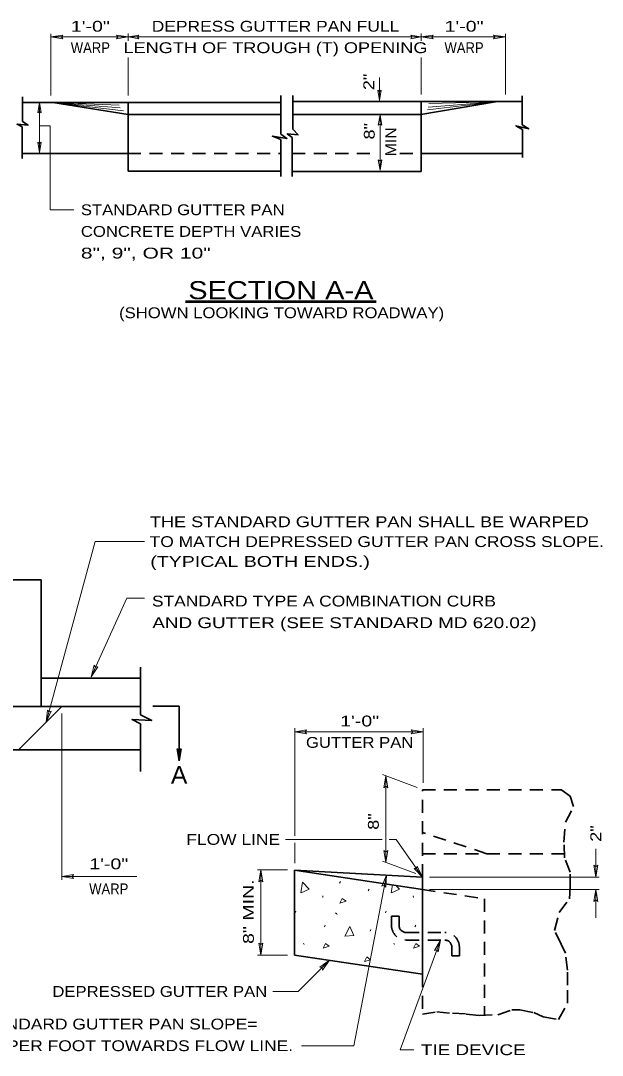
# Model space of a CAD drawing. Extents: x 16.6 to 31.7, y 5.4 to 26.
# Drawn here: x 24.24 to 31.09, y 13.23 to 25.41 of the extents above; entities that cross this region are included whole.
import ezdxf
from ezdxf.enums import TextEntityAlignment as Align

# ---------------------------------------------------------------- set-up
doc = ezdxf.new("R2010")
doc.units = 0
doc.header["$LTSCALE"] = 0.051
doc.linetypes.add('MEDIUM_DASHED', pattern=[4.5, 3, -1.5])
for name, color, linetype, lineweight in [('1', 7, 'Continuous', 35), ('10', 7, 'Continuous', 13), ('12', 7, 'Continuous', 53), ('13', 7, 'Continuous', 53), ('6', 7, 'Continuous', 13)]:
    doc.layers.add(name, color=color, linetype=linetype, lineweight=lineweight)

msp = doc.modelspace()

# ---------------------------------------------------------------- linework, layer by layer
at = {"layer": '1'}
for p, q in [((24.26392, 24.22625), (24.26392, 24.51833)), ((27.30342, 24.07883), (27.30342, 24.53325)), ((27.44408, 24.13575), (27.44408, 24.53325)), ((30.14442, 24.18958), (30.14442, 24.53058)), ((24.26875, 24.45258), (27.29925, 24.45258)), ((25.509, 24.30858), (24.62108, 24.45167)), ((25.51, 23.64292), (25.51, 24.44658)), ((27.44858, 24.46108), (30.14583, 24.46108)), ((28.95183, 24.31083), (29.82983, 24.45925)), ((28.95633, 23.63992), (28.95633, 24.46108)), ((25.509, 24.30858), (27.29758, 24.30858)), ((27.44217, 24.31083), (28.95183, 24.31083)), ((24.26208, 23.79), (24.26208, 24.16542)), ((30.14808, 23.80342), (30.14808, 24.133)), ((27.30567, 23.57792), (27.30567, 24.0135)), ((27.4395, 23.57792), (27.4395, 24.03975)), ((24.25933, 23.852), (25.5065, 23.852)), ((28.95933, 23.852), (30.1435, 23.852)), ((25.51, 23.64292), (27.30467, 23.64292)), ((27.43967, 23.63992), (28.95633, 23.63992)), ((24.48625, 18.82992), (19.43833, 18.82992)), ((24.48625, 17.33783), (24.48625, 18.82992)), ((25.65375, 17.24208), (25.65375, 17.80275)), ((25.65375, 17.67183), (24.48625, 17.67183)), ((17.99208, 17.33783), (25.65375, 17.33783)), ((24.22067, 16.8315), (24.727, 17.33783)), ((25.65333, 16.57325), (25.65333, 17.13392)), ((25.65333, 16.82675), (17.98792, 16.82675)), ((27.46475, 14.41217), (27.46475, 15.41217)), ((28.9705, 15.32908), (27.46475, 15.41217)), ((27.46475, 15.41217), (28.97017, 15.18408)), ((28.97017, 14.18642), (28.97017, 15.32908)), ((28.97017, 14.18642), (27.46475, 14.41217))]:
    msp.add_line(p, q, dxfattribs=at)
at = {"layer": '1', "linetype": 'MEDIUM_DASHED'}
for p, q in [((25.5065, 23.852), (27.30567, 23.852)), ((27.4395, 23.852), (28.42958, 23.852)), ((28.70233, 23.852), (28.95633, 23.852)), ((28.97017, 16.35567), (30.61067, 16.35567)), ((28.97017, 15.32908), (28.97017, 16.35567)), ((29.72633, 15.60483), (28.97017, 15.85692)), ((28.97017, 15.60483), (30.64092, 15.60483)), ((28.97017, 15.18392), (29.7005, 15.07333)), ((29.7005, 15.07333), (29.7005, 13.69533)), ((28.60692, 14.76075), (28.60692, 14.87092)), ((28.60692, 14.87092), (28.69567, 14.87092)), ((28.69567, 14.76075), (28.69567, 14.87092)), ((28.779, 14.67742), (29.23542, 14.67742)), ((28.779, 14.58867), (29.23242, 14.58867)), ((29.31575, 14.50533), (29.31575, 14.40183)), ((29.4045, 14.50533), (29.4045, 14.40183)), ((29.31575, 14.40183), (29.4045, 14.40183)), ((28.97017, 14.18642), (28.97017, 13.71692))]:
    msp.add_line(p, q, dxfattribs=at)
at = {"layer": '1'}
for points in [[(27.4395, 24.03975), (27.38025, 24.08283), (27.507, 24.06875), (27.44408, 24.13575)], [(27.30567, 24.0135), (27.20583, 24.05292), (27.37533, 24.028), (27.30342, 24.07883)]]:
    msp.add_lwpolyline(points, dxfattribs=at)
at = {"layer": '1', "linetype": 'MEDIUM_DASHED'}
msp.add_lwpolyline([(28.97017, 13.71692), (29.13767, 13.74208), (29.32375, 13.72592), (29.48567, 13.71783), (29.63942, 13.70167), (29.858, 13.70983), (30.01992, 13.76617), (30.117, 13.76617), (30.27892, 13.73392), (30.39217, 13.68558), (30.57025, 13.65333), (30.67542, 13.84683), (30.67542, 14.05658), (30.67542, 14.23392), (30.65117, 14.43558), (30.60267, 14.54033), (30.52167, 14.70158), (30.57825, 14.91133), (30.69975, 15.07258), (30.70775, 15.20967), (30.70775, 15.38708), (30.643, 15.55642), (30.635, 15.74183), (30.65117, 15.97567), (30.74825, 16.16117), (30.70775, 16.28217), (30.61067, 16.35467)], dxfattribs=at)
for centre, radius, start, end in [((28.779, 14.76075), 0.17208, 180, 270), ((28.779, 14.76075), 0.08333, 180, 270), ((29.23242, 14.50533), 0.17211, 0, 90), ((29.23242, 14.50533), 0.08333, 0, 90)]:
    msp.add_arc(centre, radius, start, end, dxfattribs=at)
at = {"layer": '10'}
for p, q in [((24.60033, 24.535), (24.60033, 25.25742)), ((24.74033, 25.2455), (24.60033, 25.22217)), ((25.51, 25.22217), (24.60033, 25.22217)), ((24.74033, 25.19883), (24.60033, 25.22217)), ((24.74033, 25.2455), (24.72283, 25.22217)), ((24.74033, 25.19883), (24.72283, 25.22217)), ((25.37, 25.2455), (25.51, 25.22217)), ((25.37, 25.2455), (25.3875, 25.22217)), ((25.37, 25.19883), (25.51, 25.22217)), ((25.37, 25.19883), (25.3875, 25.22217)), ((25.51, 25.17658), (25.51, 25.26333)), ((25.63358, 25.24217), (25.51358, 25.22217)), ((25.51358, 25.22217), (28.95175, 25.22217)), ((25.63358, 25.20217), (25.51358, 25.22217)), ((25.63358, 25.24217), (25.61858, 25.22217)), ((25.63358, 25.20217), (25.61858, 25.22217)), ((28.83175, 25.24217), (28.95175, 25.22217)), ((28.83175, 25.24217), (28.84675, 25.22217)), ((28.83175, 25.20217), (28.95175, 25.22217)), ((28.83175, 25.20217), (28.84675, 25.22217)), ((28.95633, 25.17658), (28.95633, 25.26333)), ((29.09633, 25.2455), (28.95633, 25.22217)), ((28.95633, 25.22217), (29.94533, 25.22217)), ((29.09633, 25.19883), (28.95633, 25.22217)), ((29.09633, 25.2455), (29.07883, 25.22217)), ((29.09633, 25.19883), (29.07883, 25.22217)), ((29.80533, 25.2455), (29.94533, 25.22217)), ((29.80533, 25.2455), (29.82283, 25.22217)), ((29.80533, 25.19883), (29.94533, 25.22217)), ((29.80533, 25.19883), (29.82283, 25.22217)), ((29.94533, 24.54442), (29.94533, 25.25742)), ((25.51, 24.535), (25.51, 24.97967)), ((28.95633, 24.54442), (28.95633, 24.97967)), ((28.46508, 24.476), (28.46508, 24.74675)), ((28.44508, 24.596), (28.46508, 24.476)), ((28.44508, 24.596), (28.46508, 24.581)), ((28.48508, 24.596), (28.46508, 24.476)), ((28.48508, 24.596), (28.46508, 24.581)), ((24.44442, 24.331), (24.46442, 24.451)), ((24.46442, 23.86208), (24.46442, 24.451)), ((24.48442, 24.331), (24.46442, 24.451)), ((24.44442, 24.331), (24.46442, 24.346)), ((24.48442, 24.331), (24.46442, 24.346)), ((28.45125, 24.18242), (28.47125, 24.30242)), ((28.47125, 23.65458), (28.47125, 24.30242)), ((28.49125, 24.18242), (28.47125, 24.30242)), ((28.45125, 24.18242), (28.47125, 24.19742)), ((28.49125, 24.18242), (28.47125, 24.19742)), ((24.44442, 23.98208), (24.46442, 23.86208)), ((24.44442, 23.98208), (24.46442, 23.96708)), ((24.48442, 23.98208), (24.46442, 23.86208)), ((24.48442, 23.98208), (24.46442, 23.96708)), ((28.45125, 23.77458), (28.47125, 23.65458)), ((28.45125, 23.77458), (28.47125, 23.75958)), ((28.49125, 23.77458), (28.47125, 23.65458)), ((28.49125, 23.77458), (28.47125, 23.75958)), ((24.86875, 23.18758), (24.59108, 23.18758)), ((25.11917, 19.28025), (24.54517, 17.156)), ((25.11917, 19.28025), (25.70267, 19.28025)), ((25.49433, 18.6125), (25.0715, 17.68892)), ((25.49433, 18.6125), (25.70267, 18.6125)), ((25.10858, 17.82592), (25.0715, 17.68892)), ((25.151, 17.8065), (25.0715, 17.68892)), ((25.10858, 17.82592), (25.1225, 17.80033)), ((25.151, 17.8065), (25.1225, 17.80033)), ((24.55917, 17.29725), (24.54517, 17.156)), ((24.60425, 17.28508), (24.54517, 17.156)), ((24.55917, 17.29725), (24.57708, 17.27425)), ((24.60425, 17.28508), (24.57708, 17.27425)), ((24.727, 15.29667), (24.727, 17.2545)), ((27.46825, 17.08325), (27.46825, 15.81517)), ((27.60825, 17.06492), (27.46825, 17.04158)), ((27.60825, 17.06492), (27.46825, 17.04158)), ((27.60825, 17.06492), (27.59075, 17.04158)), ((27.60825, 17.06492), (27.59075, 17.04158)), ((28.83792, 17.06492), (28.97792, 17.04158)), ((28.83792, 17.06492), (28.85542, 17.04158)), ((28.97792, 16.439), (28.97792, 17.08325)), ((27.46825, 17.04158), (28.97792, 17.04158)), ((27.60825, 17.01825), (27.46825, 17.04158)), ((27.60825, 17.01825), (27.46825, 17.04158)), ((27.60825, 17.01825), (27.59075, 17.04158)), ((27.60825, 17.01825), (27.59075, 17.04158)), ((28.83792, 17.01825), (28.97792, 17.04158)), ((28.83792, 17.01825), (28.85542, 17.04158)), ((28.90975, 16.38458), (28.49967, 16.53633)), ((28.51542, 16.38192), (28.53875, 16.52192)), ((28.51542, 16.38192), (28.53875, 16.52192)), ((28.53875, 15.50192), (28.53875, 16.52192)), ((28.56208, 16.38192), (28.53875, 16.52192)), ((28.56208, 16.38192), (28.53875, 16.52192)), ((28.51542, 16.38192), (28.53875, 16.39942)), ((28.51542, 16.38192), (28.53875, 16.39942)), ((28.56208, 16.38192), (28.53875, 16.39942)), ((28.56208, 16.38192), (28.53875, 16.39942)), ((27.36117, 15.7735), (28.49708, 15.7735)), ((27.46825, 15.4955), (27.46825, 15.73183)), ((28.66075, 15.7735), (28.58042, 15.7735)), ((28.66075, 15.7735), (28.9705, 15.32975)), ((28.51542, 15.64192), (28.53875, 15.50192)), ((28.51542, 15.64192), (28.53875, 15.62442)), ((28.56208, 15.64192), (28.53875, 15.50192)), ((28.56208, 15.64192), (28.53875, 15.62442)), ((31.009, 15.32908), (31.009, 15.66242)), ((28.89242, 15.37108), (28.49967, 15.51642)), ((24.867, 15.36183), (24.727, 15.33833)), ((24.867, 15.36183), (24.8495, 15.33842)), ((27.38142, 15.4145), (27.02967, 15.4145)), ((27.04692, 15.2745), (27.07025, 15.4145)), ((27.04692, 15.2745), (27.07025, 15.4145)), ((27.07025, 15.4145), (27.07025, 14.41217)), ((27.09358, 15.2745), (27.07025, 15.4145)), ((27.09358, 15.2745), (27.07025, 15.4145)), ((28.548, 15.35242), (28.16467, 13.34433)), ((28.49383, 15.22125), (28.548, 15.35242)), ((28.53933, 15.21075), (28.548, 15.35242)), ((28.87125, 15.43117), (28.9705, 15.32975)), ((28.87125, 15.43117), (28.90033, 15.43017)), ((28.9095, 15.45792), (28.90033, 15.43017)), ((28.9095, 15.45792), (28.9705, 15.32975)), ((30.98567, 15.46908), (31.009, 15.32908)), ((30.98567, 15.46908), (31.009, 15.45158)), ((31.03233, 15.46908), (31.009, 15.32908)), ((31.03233, 15.46908), (31.009, 15.45158)), ((24.867, 15.31517), (24.727, 15.33833)), ((24.727, 15.33833), (25.61125, 15.33833)), ((24.867, 15.31517), (24.8495, 15.33842)), ((27.04692, 15.2745), (27.07025, 15.292)), ((27.04692, 15.2745), (27.07025, 15.292)), ((27.09358, 15.2745), (27.07025, 15.292)), ((27.09358, 15.2745), (27.07025, 15.292)), ((28.49383, 15.22125), (28.5205, 15.23308)), ((28.53933, 15.21075), (28.5205, 15.23308)), ((29.0535, 15.32908), (31.05067, 15.32908)), ((29.0535, 15.18392), (31.05067, 15.18392)), ((30.98567, 15.04392), (31.009, 15.18392)), ((31.009, 15.18392), (31.009, 14.85058)), ((31.03233, 15.04392), (31.009, 15.18392)), ((30.98567, 15.04392), (31.009, 15.06142)), ((31.03233, 15.04392), (31.009, 15.06142)), ((27.04692, 14.55217), (27.07025, 14.41217)), ((27.04692, 14.55217), (27.07025, 14.53467)), ((27.09358, 14.55217), (27.07025, 14.41217)), ((27.09358, 14.55217), (27.07025, 14.53467)), ((29.182, 14.58867), (28.70625, 13.297)), ((29.11175, 14.46533), (29.182, 14.58867)), ((29.1555, 14.44925), (29.182, 14.58867)), ((27.38142, 14.41217), (27.02967, 14.41217)), ((29.11175, 14.46533), (29.13967, 14.47375)), ((29.1555, 14.44925), (29.13967, 14.47375)), ((27.8775, 14.35025), (27.50867, 13.98283)), ((27.76183, 14.268), (27.8775, 14.35025)), ((27.76183, 14.268), (27.79075, 14.26383)), ((27.79475, 14.23492), (27.79075, 14.26383)), ((27.79475, 14.23492), (27.8775, 14.35025)), ((27.21, 13.98283), (27.50867, 13.98283)), ((27.54933, 13.34433), (28.16467, 13.34433)), ((28.70625, 13.297), (28.86925, 13.297))]:
    msp.add_line(p, q, dxfattribs=at)
at = {"layer": '10', "lineweight": 35}
for p, q in [((26.108, 17.3435), (25.80017, 17.3435)), ((26.108, 17.3435), (26.108, 16.69908)), ((26.08467, 16.83908), (26.108, 16.69908)), ((26.08467, 16.83908), (26.108, 16.82158)), ((26.13133, 16.83908), (26.108, 16.69908)), ((26.13133, 16.83908), (26.108, 16.82158))]:
    msp.add_line(p, q, dxfattribs=at)
for points in [[(24.26208, 24.16542), (24.202, 24.19475), (24.33175, 24.1855), (24.26392, 24.22625)], [(30.14808, 24.133), (30.07067, 24.17792), (30.21992, 24.14108), (30.14442, 24.18958)], [(25.65333, 17.13392), (25.55508, 17.18533), (25.78575, 17.17317), (25.65375, 17.24208)]]:
    msp.add_lwpolyline(points, dxfattribs=at)
at = {"layer": '10'}
msp.add_lwpolyline([(24.46442, 24.17792), (24.59108, 24.17792), (24.59108, 23.18758)], dxfattribs=at)
at = {"layer": '12'}
msp.add_line((26.1835, 22.10783), (28.42583, 22.10783), dxfattribs=at)
at = {"layer": '6'}
for p, q in [((24.62108, 24.45167), (25.41525, 24.38692)), ((24.62108, 24.45167), (25.4545, 24.35333)), ((24.62108, 24.45167), (25.4035, 24.42033)), ((29.82983, 24.45925), (29.029, 24.36333)), ((29.82983, 24.45925), (29.03883, 24.39667)), ((29.82983, 24.45925), (29.04492, 24.43742)), ((27.99592, 15.25733), (28.00483, 15.27725)), ((28.6035, 15.14333), (28.61658, 15.23767)), ((27.79775, 15.1105), (27.8, 15.0905)), ((28.33333, 15.16625), (28.34225, 15.18625)), ((28.86117, 15.1105), (28.86342, 15.0905)), ((27.472, 14.90875), (27.48083, 14.92875)), ((27.94925, 14.90875), (27.95817, 14.89542)), ((27.95817, 14.90367), (27.96708, 14.89033)), ((28.53542, 14.90875), (28.54425, 14.92875)), ((27.81825, 14.74417), (27.82717, 14.76417)), ((28.88175, 14.74417), (28.89058, 14.76417)), ((28.35558, 14.69317), (28.36442, 14.71308)), ((27.56967, 14.55108), (27.5785, 14.53775)), ((28.63308, 14.55108), (28.642, 14.53775))]:
    msp.add_line(p, q, dxfattribs=at)
for points in [[(27.54, 15.14333), (27.55758, 15.27017), (27.63708, 15.18808), (27.54208, 15.14408)], [(28.65875, 15.23125), (28.70058, 15.18808), (28.6055, 15.14408)], [(28.05583, 14.63317), (28.11583, 14.74642), (28.16242, 14.64208), (28.05808, 14.63317)]]:
    msp.add_lwpolyline(points, dxfattribs=at)
for points in [[(28.00033, 15.02417), (28.027, 15.07967), (28.07142, 15.04642)], [(27.80275, 14.49333), (27.82942, 14.54883), (27.87375, 14.5155)], [(28.86617, 14.49333), (28.89283, 14.54883), (28.93725, 14.5155)], [(28.28942, 14.33467), (28.31608, 14.39017), (28.36042, 14.35683)]]:
    msp.add_lwpolyline(points, close=True, dxfattribs=at)

# ---------------------------------------------------------------- texts
at = {"layer": '12'}
for s, height, width, p in [('1\'-0"', 0.1275, 1.35, (25.06417, 25.28467)), ('DEPRESS GUTTER PAN FULL', 0.1275, 1.2, (27.24162, 25.28467)), ('1\'-0"', 0.1275, 1.35, (29.45983, 25.28467)), ('WARP', 0.1275, 0.9, (25.06408, 25.03217)), ('LENGTH OF TROUGH (T) OPENING', 0.1275, 1.25, (27.24158, 25.03217)), ('WARP', 0.1275, 0.9, (29.45975, 25.03217)), ('SECTION A-A', 0.2125, 1.2, (27.30471, 22.13458)), ('(SHOWN LOOKING TOWARD ROADWAY)', 0.1275, 1.15, (27.31362, 21.91117)), ('1\'-0"', 0.1275, 1.35, (28.232, 17.10408)), ('GUTTER PAN', 0.1275, 1.15, (28.232, 16.85158)), ('1\'-0"', 0.1275, 1.35, (25.2805, 15.42167)), ('WARP', 0.1275, 0.9, (25.28042, 15.1275))]:
    msp.add_text(s, height=height, dxfattribs=dict(at, width=width)).set_placement(p, align=Align.CENTER)
for s, width, p in [('2"', 1.25, (28.40258, 24.69317)), ('8"', 1.25, (28.40875, 24.11242)), ('MIN', 1.1, (28.66125, 23.9875)), ('8"', 1.25, (28.45642, 15.98404)), ('8" MIN.', 1.35, (26.98683, 14.92237))]:
    msp.add_text(s, height=0.1275, rotation=90, dxfattribs=dict(at, width=width)).set_placement(p, align=Align.CENTER)
for s, width, p in [('STANDARD GUTTER PAN', 1.15, (24.95208, 23.12383)), ('CONCRETE DEPTH VARIES', 1.15, (24.95208, 22.86883)), ('8", 9", OR 10"', 1.45, (24.95208, 22.61383)), (' THE STANDARD GUTTER PAN SHALL BE WARPED ', 1.25, (25.7045, 19.45017)), (' TO MATCH DEPRESSED GUTTER PAN CROSS SLOPE.', 1.2, (25.7045, 19.21642)), (' (TYPICAL BOTH ENDS.)', 1.35, (25.7045, 18.98267)), (' STANDARD TYPE A COMBINATION CURB', 1.2, (25.73158, 18.51625)), (' AND GUTTER (SEE STANDARD MD 620.02)', 1.3, (25.73158, 18.26125)), ('STANDARD GUTTER PAN SLOPE=', 1.2, (23.67, 13.53558)), ('1/2" PER FOOT TOWARDS FLOW LINE.', 1.2, (23.67, 13.28058)), ('TIE DEVICE', 1.3, (28.95258, 13.23325))]:
    msp.add_text(s, height=0.1275, dxfattribs=dict(at, width=width)).set_placement(p)
for s, width, p in [('FLOW LINE', 1.2, (27.29575, 15.70975)), ('DEPRESSED GUTTER PAN', 1.15, (27.14458, 13.91908))]:
    msp.add_text(s, height=0.1275, dxfattribs=dict(at, width=width)).set_placement(p, align=Align.RIGHT)
at = {"layer": '12', "width": 1.25}
msp.add_text('2"', height=0.1275, rotation=90, dxfattribs=at).set_placement((31.07275, 15.74567))
at = {"layer": '13', "width": 1.05}
msp.add_text('A', height=0.2068, dxfattribs=at).set_placement((26.108, 16.42975), align=Align.CENTER)

doc.saveas('drawing.dxf')
